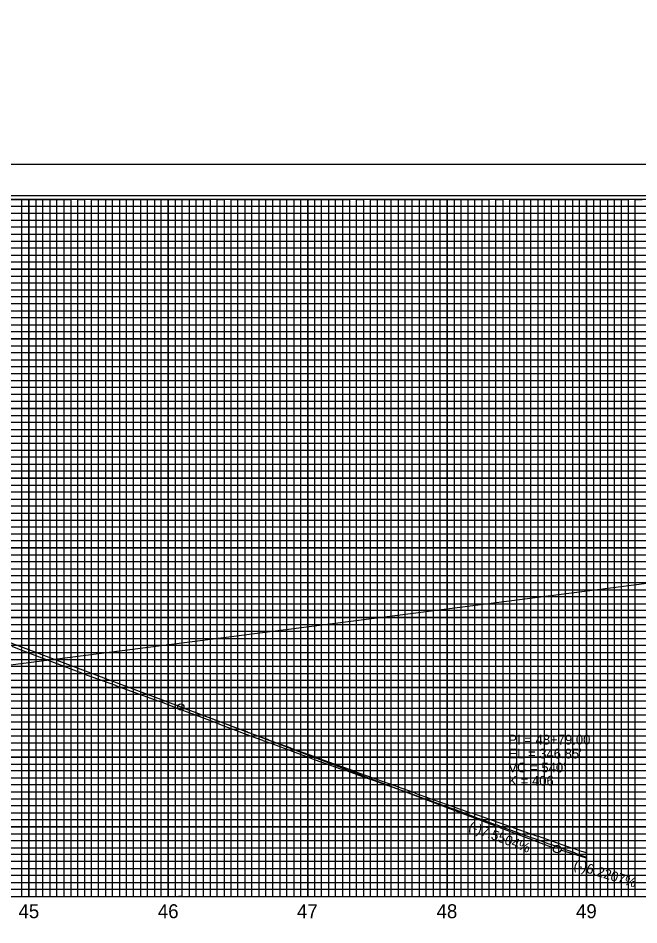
# Model space of a CAD drawing. Extents: x 571503 to 593215, y -77195 to -51828.
# Drawn here: x 584526 to 584971, y -53129 to -52479 of the extents above; entities that cross this region are included whole.
import ezdxf

# ---------------------------------------------------------------- set-up
doc = ezdxf.new("R2010")
doc.units = 0
for name, color, linetype in [('Exist Vertical Profile Ground Line', 7, 'Continuous'), ('Exist Vertical Profile Horizontal Axis Label Major', 7, 'Continuous'), ('Prop PFL Text', 7, 'Continuous'), ('Prop Vertical Profile Curve Label', 7, 'Continuous'), ('Prop Vertical Profile Grade', 7, 'Continuous'), ('Prop Vertical Profile Grade Label', 7, 'Continuous'), ('Prop VPI Label', 7, 'Continuous'), ('Sheet Clip Boundary CELL', 7, 'Continuous'), ('Sheet DOT Grid CELL', 7, 'Continuous'), ('Sheet Plot Border Inside CELL', 7, 'Continuous'), ('Sheet Plot Border Outside CELL', 7, 'Continuous'), ('Sheet Profile CELL', 7, 'Continuous'), ('Sheet Profile Grid Major CELL', 7, 'Continuous'), ('Sheet Profile Grid Middle CELL', 7, 'Continuous'), ('Sheet Profile Grid Minor CELL', 7, 'Continuous')]:
    doc.layers.add(name, color=color, linetype=linetype)

msp = doc.modelspace()

# ---------------------------------------------------------------- linework, layer by layer
at = {"layer": 'Exist Vertical Profile Ground Line'}
for points in [[(584521.09, -52929.24), (584526.3, -52931.24), (584535.57, -52934.8), (584542.49, -52937.45), (584542.51, -52937.46), (584573.99, -52949.55), (584574.41, -52949.71), (584595.26, -52957.24), (584595.46, -52957.32), (584626.44, -52968.51), (584627.62, -52968.93), (584637.77, -52972.81), (584643.52, -52975.02), (584648.77, -52977.02), (584649.27, -52977.2), (584650.04, -52977.47), (584655.03, -52979.37), (584660.78, -52981.56), (584666.53, -52983.76), (584672.28, -52985.95), (584678.03, -52988.14), (584678.9, -52988.47), (584682.13, -52989.68), (584683.78, -52990.3), (584689.53, -52992.44), (584695.28, -52994.58), (584700.76, -52996.62), (584701.04, -52996.73), (584702.41, -52997.24), (584706.09, -52998.58), (584706.79, -52998.84), (584712.54, -53000.98), (584718.29, -53003.12), (584724.04, -53005.26), (584729.79, -53007.39), (584734.31, -53009.07), (584735.54, -53009.52), (584736.69, -53009.94), (584741.29, -53011.58), (584747.04, -53013.62), (584752.8, -53015.66), (584756.67, -53017.04), (584758.55, -53017.66), (584760.77, -53018.4), (584764.3, -53019.65), (584770.05, -53021.69), (584775.8, -53023.73), (584781.55, -53025.77), (584787.3, -53027.81), (584788.6, -53028.27), (584789.41, -53028.57), (584793.05, -53029.81), (584793.58, -53029.99), (584796.21, -53030.99), (584798.81, -53031.91), (584804.56, -53033.97), (584804.94, -53034.11), (584810.31, -53036.04), (584816.06, -53038.1), (584818.95, -53039.14), (584821.81, -53040.16), (584822.36, -53040.36)], [(584822.36, -53040.36), (584827.56, -53042.23), (584833.31, -53044.29), (584839.06, -53046.36), (584843.02, -53047.78), (584844.81, -53048.46), (584850.57, -53050.66), (584855.29, -53052.46), (584856.32, -53052.83), (584862.07, -53054.89), (584867.82, -53056.96), (584869.11, -53057.42), (584873.57, -53059.12), (584874.26, -53059.39), (584879.32, -53061.21), (584885.07, -53063.28), (584890.82, -53065.35), (584892.81, -53066.06), (584896.58, -53067.39), (584902.33, -53069.42), (584906.32, -53070.83), (584908.08, -53071.45), (584913.83, -53073.51), (584917.52, -53074.82), (584919.58, -53075.55), (584924.33, -53077.23), (584925.33, -53077.58), (584933.23, -53080.4)]]:
    msp.add_lwpolyline(points, dxfattribs=at)
at = {"layer": 'Prop PFL Text'}
msp.add_line((571799.62, -54572.45), (593215.36, -51828.37), dxfattribs=at)
at = {"layer": 'Prop Vertical Profile Curve Label'}
msp.add_circle((584642.23, -52972.77), 2.25, dxfattribs=at)
at = {"layer": 'Prop Vertical Profile Grade'}
msp.add_line((584384.73, -52875.56), (584642.23, -52972.77), dxfattribs=at)
msp.add_spline([(584642.23, -52972.77), (584653.03, -52976.84), (584663.83, -52980.89), (584674.63, -52984.94), (584685.43, -52988.96), (584696.23, -52992.98), (584707.03, -52996.97), (584717.83, -53000.96), (584728.63, -53004.93), (584739.43, -53008.88), (584750.23, -53012.82), (584761.03, -53016.75), (584771.83, -53020.66), (584782.63, -53024.56), (584793.43, -53028.44), (584804.23, -53032.31), (584815.03, -53036.17), (584825.83, -53040.01), (584836.63, -53043.83), (584847.43, -53047.64), (584858.23, -53051.44), (584869.03, -53055.22), (584879.83, -53058.99), (584890.63, -53062.75), (584901.43, -53066.49), (584912.23, -53070.21), (584923.03, -53073.92), (584933.23, -53077.41)], degree=3, dxfattribs=at)
at = {"layer": 'Prop VPI Label'}
for p, q in [((584642.23, -52972.77), (584909.66, -53073.73)), ((584933.23, -53081.23), (584914.86, -53075.52))]:
    msp.add_line(p, q, dxfattribs=at)
msp.add_circle((584912.23, -53074.7), 2.75, dxfattribs=at)
at = {"layer": 'Sheet Clip Boundary CELL'}
msp.add_lwpolyline([(583833.23, -52608.7), (583833.23, -53108.7), (585233.23, -53108.7), (585233.23, -52746.25), (585083.18, -52746.25), (585083.18, -52608.7)], close=True, dxfattribs=at)
at = {"layer": 'Sheet DOT Grid CELL'}
for p, q in [((584533.23, -53108.7), (584533.23, -52608.7)), ((584533.23, -53108.7), (584533.23, -52608.7)), ((584583.23, -53108.7), (584583.23, -52608.7)), ((584583.23, -53108.7), (584583.23, -52608.7)), ((584633.23, -53108.7), (584633.23, -52608.7)), ((584633.23, -53108.7), (584633.23, -52608.7)), ((584683.23, -53108.7), (584683.23, -52608.7)), ((584683.23, -53108.7), (584683.23, -52608.7)), ((584733.23, -53108.7), (584733.23, -52608.7)), ((584733.23, -53108.7), (584733.23, -52608.7)), ((584783.23, -53108.7), (584783.23, -52608.7)), ((584783.23, -53108.7), (584783.23, -52608.7)), ((584833.23, -53108.7), (584833.23, -52608.7)), ((584833.23, -53108.7), (584833.23, -52608.7)), ((584883.23, -53108.7), (584883.23, -52608.7)), ((584883.23, -53108.7), (584883.23, -52608.7)), ((584933.23, -53108.7), (584933.23, -52608.7)), ((584933.23, -53108.7), (584933.23, -52608.7)), ((583783.23, -52658.7), (585083.18, -52658.7)), ((585083.18, -52658.7), (583783.23, -52658.7)), ((583783.23, -52708.7), (585083.18, -52708.7)), ((585083.18, -52708.7), (583783.23, -52708.7)), ((583783.23, -52758.7), (585283.23, -52758.7)), ((585283.23, -52758.7), (583783.23, -52758.7)), ((583783.23, -52808.7), (585283.23, -52808.7)), ((585283.23, -52808.7), (583783.23, -52808.7)), ((583783.23, -52858.7), (585283.23, -52858.7)), ((585283.23, -52858.7), (583783.23, -52858.7)), ((583783.23, -52908.7), (585283.23, -52908.7)), ((585283.23, -52908.7), (583783.23, -52908.7)), ((583783.23, -52958.7), (585283.23, -52958.7)), ((585283.23, -52958.7), (583783.23, -52958.7)), ((583783.23, -53008.7), (585283.23, -53008.7)), ((585283.23, -53008.7), (583783.23, -53008.7)), ((583783.23, -53058.7), (585283.23, -53058.7)), ((585283.23, -53058.7), (583783.23, -53058.7))]:
    msp.add_line(p, q, dxfattribs=at)
at = {"layer": 'Sheet Plot Border Inside CELL'}
msp.add_lwpolyline([(583629.23, -53661.25), (585295.73, -53661.25), (585295.73, -52606.15), (583629.23, -52606.15)], close=True, dxfattribs=at)
at = {"layer": 'Sheet Plot Border Outside CELL'}
msp.add_lwpolyline([(583616.23, -53683.7), (585300.23, -53683.7), (585300.23, -52583.7), (583616.23, -52583.7)], close=True, dxfattribs=at)
at = {"layer": 'Sheet Profile CELL'}
for p, q in [((585300.23, -52583.7), (583616.23, -52583.7)), ((583783.23, -53108.7), (585283.23, -53108.7))]:
    msp.add_line(p, q, dxfattribs=at)
msp.add_lwpolyline([(585283.23, -52608.7), (583783.23, -52608.7), (583783.23, -53658.7), (585283.23, -53658.7)], close=True, dxfattribs=at)
at = {"layer": 'Sheet Profile Grid Major CELL'}
for points in [[(584483.23, -52608.7), (584533.23, -52608.7), (584533.23, -53108.7), (584583.23, -53108.7), (584583.23, -52608.7), (584633.23, -52608.7), (584633.23, -53108.7), (584683.23, -53108.7), (584683.23, -52608.7), (584733.23, -52608.7), (584733.23, -53108.7), (584783.23, -53108.7), (584783.23, -52608.7), (584833.23, -52608.7), (584833.23, -53108.7), (584883.23, -53108.7), (584883.23, -52608.7), (584933.23, -52608.7), (584933.23, -53108.7), (584983.23, -53108.7)], [(583783.23, -52658.7), (585083.23, -52658.7)], [(585083.23, -52708.7), (583783.23, -52708.7), (583783.23, -52758.7), (585283.23, -52758.7)], [(585283.23, -52808.7), (583783.23, -52808.7), (583783.23, -52858.7), (585283.23, -52858.7)], [(585283.23, -52908.7), (583783.23, -52908.7), (583783.23, -52958.7), (585283.23, -52958.7)], [(585283.23, -53008.7), (583783.23, -53008.7), (583783.23, -53008.7), (583783.23, -53058.7), (585283.23, -53058.7)]]:
    msp.add_lwpolyline(points, dxfattribs=at)
at = {"layer": 'Sheet Profile Grid Middle CELL'}
msp.add_line((583783.23, -52633.7), (585083.18, -52633.7), dxfattribs=at)
for points in [[(584508.23, -52608.7), (584558.23, -52608.7), (584558.23, -53108.7), (584608.23, -53108.7), (584608.23, -52608.7), (584658.23, -52608.7), (584658.23, -53108.7), (584708.23, -53108.7), (584708.23, -52608.7), (584758.23, -52608.7), (584758.23, -53108.7), (584808.23, -53108.7), (584808.23, -52608.7), (584858.23, -52608.7), (584858.23, -53108.7), (584908.23, -53108.7), (584908.23, -52608.7), (584958.23, -52608.7), (584958.23, -53108.7), (585008.23, -53108.7)], [(585083.23, -52683.7), (583783.23, -52683.7), (583783.23, -52733.7), (585083.23, -52733.7)], [(585283.23, -52783.7), (583783.23, -52783.7), (583783.23, -52833.7), (585108.23, -52833.7)], [(585283.23, -52883.7), (583783.23, -52883.7), (583783.23, -52933.7), (585283.23, -52933.7)], [(585283.23, -52983.7), (583783.23, -52983.7), (583783.23, -53033.7), (585283.23, -53033.7)], [(585283.23, -53083.7), (583783.23, -53083.7)]]:
    msp.add_lwpolyline(points, dxfattribs=at)
at = {"layer": 'Sheet Profile Grid Minor CELL'}
for p, q in [((583833.23, -52613.7), (585083.23, -52613.7)), ((585083.23, -52618.7), (583833.23, -52619.05)), ((583833.23, -52623.7), (585083.23, -52623.7)), ((585083.18, -52743.7), (583833.23, -52743.7)), ((585233.23, -52748.7), (583833.23, -52748.7)), ((585233.23, -52753.7), (583833.23, -52753.7)), ((583833.23, -52763.7), (585233.23, -52763.7)), ((585233.23, -52768.7), (583833.23, -52768.7)), ((583833.23, -52773.7), (585233.23, -52773.7)), ((585233.23, -52793.7), (583833.23, -52793.7)), ((583833.23, -52798.7), (585233.23, -52798.7)), ((585233.23, -52818.7), (583833.23, -52818.7)), ((583833.23, -52823.7), (585233.23, -52823.7)), ((585233.23, -52843.7), (583833.23, -52843.7)), ((583833.23, -52848.7), (585233.23, -52848.7)), ((585233.23, -52853.7), (583833.23, -52853.7)), ((583833.23, -52863.7), (585233.23, -52863.7)), ((585233.23, -52868.7), (583833.23, -52868.7)), ((583833.23, -52873.7), (585233.23, -52873.7)), ((585233.23, -52878.7), (583833.23, -52878.7)), ((583833.23, -52888.7), (585233.23, -52888.7)), ((585233.23, -52893.7), (583833.23, -52893.7)), ((583833.23, -52898.7), (585233.23, -52898.7)), ((585233.23, -52903.7), (583833.23, -52903.7)), ((583833.23, -52913.7), (585233.23, -52913.7)), ((585233.23, -52918.7), (583833.23, -52918.7)), ((583833.23, -52923.7), (585233.23, -52923.7)), ((585233.23, -52928.7), (583833.23, -52928.7)), ((583833.23, -52938.7), (585233.23, -52938.7)), ((585233.23, -52943.7), (583833.23, -52943.7)), ((583833.23, -52948.7), (585233.23, -52948.7)), ((585233.23, -52953.7), (583833.23, -52953.7)), ((583833.23, -52963.7), (585233.23, -52963.7)), ((585233.23, -52968.7), (583833.23, -52968.7)), ((583833.23, -52973.7), (585233.23, -52973.7)), ((585233.23, -52978.7), (583833.23, -52978.7)), ((583833.23, -52988.7), (585233.23, -52988.7)), ((585233.23, -52993.7), (583833.23, -52993.7)), ((585233.23, -52998.7), (583833.23, -52998.7)), ((585233.23, -53003.7), (583833.23, -53003.7)), ((583833.23, -53013.7), (585233.23, -53013.7)), ((585233.23, -53018.7), (583833.23, -53018.7)), ((583833.23, -53023.7), (585233.23, -53023.7)), ((585233.23, -53028.7), (583833.23, -53028.7)), ((583833.23, -53038.7), (585233.23, -53038.7)), ((585233.23, -53043.7), (583833.23, -53043.7)), ((583833.23, -53048.7), (585233.23, -53048.7)), ((585233.23, -53053.7), (583833.23, -53053.7)), ((583833.23, -53063.7), (585233.23, -53063.7)), ((585233.23, -53068.7), (583833.23, -53068.7)), ((583833.23, -53073.7), (585233.23, -53073.7)), ((585233.23, -53078.7), (583833.23, -53078.7)), ((583833.23, -53088.7), (585233.23, -53088.7)), ((585233.23, -53093.7), (583833.23, -53093.7)), ((583833.23, -53098.7), (585233.23, -53098.7))]:
    msp.add_line(p, q, dxfattribs=at)
for points in [[(584523.23, -53108.7), (584528.23, -53108.7), (584528.23, -52608.7), (584538.23, -52608.7), (584538.23, -53108.7), (584543.23, -53108.7), (584543.23, -52608.7), (584548.23, -52608.7), (584548.23, -53108.7), (584553.23, -53108.7), (584553.23, -52608.7), (584563.23, -52608.7), (584563.23, -53108.7), (584568.23, -53108.7), (584568.23, -52608.7), (584573.23, -52608.7), (584573.23, -53108.7), (584578.23, -53108.7), (584578.23, -52608.7), (584588.23, -52608.7), (584588.23, -53108.7), (584593.23, -53108.7), (584593.23, -52608.7), (584598.23, -52608.7), (584598.23, -53108.7), (584603.23, -53108.7), (584603.23, -52608.7), (584613.23, -52608.7), (584613.23, -53108.7), (584618.23, -53108.7), (584618.23, -52608.7), (584623.23, -52608.7), (584623.23, -53108.7), (584628.23, -53108.7), (584628.23, -52608.7), (584638.23, -52608.7), (584638.23, -53108.7), (584642.93, -53108.15), (584643.23, -53108.7), (584643.23, -52608.7), (584648.23, -52608.7), (584648.23, -53108.7), (584653.23, -53108.7), (584653.23, -52608.7), (584663.23, -52608.7), (584663.23, -53108.7), (584668.23, -53108.7)], [(584668.23, -53108.7), (584668.23, -52608.7), (584673.23, -52608.7), (584673.23, -53108.7), (584678.23, -53108.7), (584678.23, -52608.7), (584688.23, -52608.7), (584688.23, -53108.7), (584693.23, -53108.7), (584693.23, -52608.7), (584698.23, -52608.7), (584698.23, -53108.7), (584703.23, -53108.7), (584703.23, -52608.7), (584713.23, -52608.7), (584713.23, -53108.7), (584718.23, -53108.7), (584718.23, -52608.7), (584723.23, -52608.7), (584723.23, -53108.7), (584728.23, -53108.7), (584728.23, -52608.7), (584738.23, -52608.7), (584738.23, -53108.7), (584743.23, -53108.7), (584743.23, -52608.7), (584748.23, -52608.7), (584748.23, -53108.7), (584753.23, -53108.7), (584753.23, -52608.7), (584763.23, -52608.7), (584763.23, -53108.7), (584768.23, -53108.7), (584768.23, -52608.7), (584773.23, -52608.7), (584773.23, -53108.7), (584778.23, -53108.7), (584778.23, -52608.7), (584788.23, -52608.7), (584788.23, -53108.7), (584793.23, -53108.7), (584793.23, -52608.7), (584798.23, -52608.7), (584798.23, -53108.7), (584803.23, -53108.7), (584803.23, -52608.7), (584813.23, -52608.7), (584813.23, -53108.7), (584818.23, -53108.7), (584818.23, -52608.7), (584823.23, -52608.7), (584823.23, -53108.7), (584828.23, -53108.7), (584828.23, -52608.7), (584838.23, -52608.7), (584838.23, -53108.7), (584843.23, -53108.7), (584843.23, -52608.7), (584848.23, -52608.7), (584848.23, -53108.7), (584853.23, -53108.7), (584853.23, -52608.7), (584863.23, -52608.7), (584863.23, -53108.7), (584868.23, -53108.7), (584868.23, -52608.7), (584873.23, -52608.7), (584873.23, -53108.7), (584878.23, -53108.7), (584878.23, -52608.7), (584888.23, -52608.7), (584888.23, -53108.7), (584893.23, -53108.7), (584893.23, -52608.7), (584898.23, -52608.7), (584898.23, -53108.7), (584903.23, -53108.7), (584903.23, -52608.7), (584913.23, -52608.7), (584913.23, -53108.7), (584918.23, -53108.7), (584918.23, -52608.7), (584923.23, -52608.7), (584923.23, -53108.7), (584928.23, -53108.7), (584928.23, -52608.7), (584938.23, -52608.7), (584938.23, -53108.7), (584943.23, -53108.7), (584943.23, -52608.7), (584948.23, -52608.7), (584948.23, -53108.7), (584953.23, -53108.7), (584953.23, -52608.7), (584963.23, -52608.7), (584963.23, -53108.7), (584968.23, -53108.7), (584968.23, -52608.7), (584973.23, -52608.7)], [(585083.23, -52628.7), (583833.23, -52628.7), (583833.23, -52638.7), (585083.23, -52638.7)], [(585083.18, -52643.7), (583833.23, -52643.7), (583833.23, -52648.7), (585083.23, -52648.7)], [(585083.23, -52653.7), (583833.23, -52653.7), (583833.23, -52663.7), (585083.23, -52663.7)], [(585083.23, -52668.7), (583833.23, -52668.7), (583833.23, -52673.7), (585083.23, -52673.7)], [(585083.23, -52678.7), (583833.23, -52678.7), (583833.23, -52688.7), (585083.23, -52688.7)], [(585083.23, -52693.7), (583833.23, -52693.7), (583833.23, -52698.7), (585083.23, -52698.7)], [(585083.23, -52703.7), (583833.23, -52703.7), (583833.23, -52713.7), (585083.23, -52713.7)], [(585083.23, -52718.8), (583833.33, -52718.8), (583833.33, -52723.7), (585083.23, -52723.7)], [(585083.23, -52728.7), (583833.23, -52728.7), (583833.23, -52738.7), (585083.23, -52738.7)], [(585233.23, -52778.7), (583833.23, -52778.7), (583833.23, -52788.7), (585233.23, -52788.7)], [(585233.23, -52803.7), (583833.23, -52803.7), (583833.23, -52813.7), (585233.23, -52813.7)], [(585233.23, -52828.7), (583833.23, -52828.7), (583833.23, -52838.7), (585233.23, -52838.7)], [(585233.23, -53103.7), (583833.23, -53103.7)]]:
    msp.add_lwpolyline(points, dxfattribs=at)

# ---------------------------------------------------------------- texts
at = {"layer": 'Exist Vertical Profile Horizontal Axis Label Major'}
for s, p in [('45', (584525.78, -53124.28)), ('46', (584625.72, -53124.28)), ('47', (584725.57, -53124.28)), ('48', (584825.7, -53124.28)), ('49', (584925.74, -53124.28))]:
    msp.add_text(s, height=10, dxfattribs=at).set_placement(p)
at = {"layer": 'Prop Vertical Profile Curve Label'}
for s, p in [("VC = 540'", (584877.23, -53019.7)), ('K = 406', (584877.23, -53029.22))]:
    msp.add_text(s, height=7, dxfattribs=at).set_placement(p)
at = {"layer": 'Prop Vertical Profile Grade Label'}
for s, rotation, p in [('(-)7.5504%', 339.31741, (584848.08, -53061.17)), ('(-)6.2207%', 342.7225, (584923.57, -53088.7))]:
    msp.add_text(s, height=7, rotation=rotation, dxfattribs=at).set_placement(p)
at = {"layer": 'Prop VPI Label'}
for s, p in [('PI = 48+79.00', (584877.23, -52999.7)), ("EL = 346.85'", (584877.23, -53009.7))]:
    msp.add_text(s, height=7, dxfattribs=at).set_placement(p)

doc.saveas('drawing.dxf')
